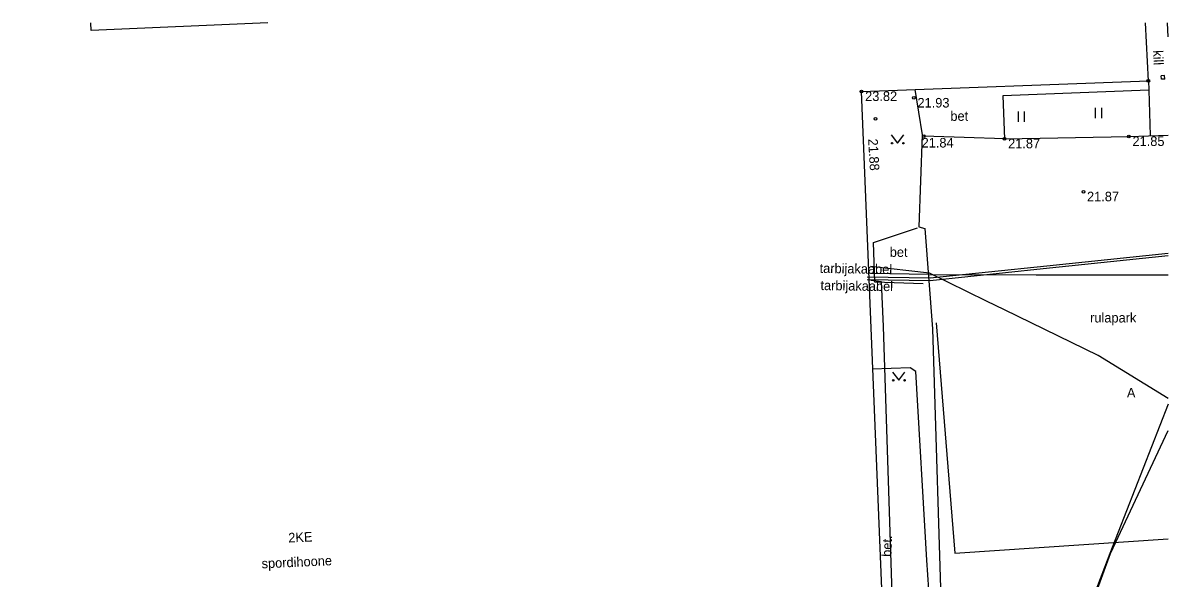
# Model space of a CAD drawing. Extents: x 714038 to 714279, y 6589845 to 6590041.
# Drawn here: x 714195.2 to 714279, y 6590000.4 to 6590041 of the extents above; entities that cross this region are included whole.
import ezdxf

# ---------------------------------------------------------------- set-up
doc = ezdxf.new("R2010")
doc.units = 0
for name, color, linetype in [('AED', 7, 'Continuous'), ('HALJASTUS', 7, 'Continuous'), ('HOONE', 7, 'Continuous'), ('HOONEDET', 7, 'Continuous'), ('KORGUS', 7, 'Continuous'), ('KPKAABEL', 7, 'Continuous'), ('MPKAABEL', 7, 'Continuous'), ('RAJATIS', 7, 'Continuous'), ('TEE', 7, 'Continuous'), ('VTRASS', 7, 'Continuous')]:
    doc.layers.add(name, color=color, linetype=linetype)

msp = doc.modelspace()

# ---------------------------------------------------------------- linework, layer by layer
at = {"layer": 'AED'}
for p, q in [((714278.696, 6590037.106), (714278.446, 6590037.094)), ((714278.458, 6590036.844), (714278.446, 6590037.094)), ((714278.708, 6590036.856), (714278.696, 6590037.106)), ((714278.708, 6590036.856), (714278.458, 6590036.844))]:
    msp.add_line(p, q, dxfattribs=at)
at = {"layer": 'HALJASTUS'}
for p, q in [((714267.973, 6590034.478), (714267.973, 6590033.717)), ((714268.428, 6590034.478), (714268.428, 6590033.717)), ((714273.624, 6590034.747), (714273.624, 6590033.986)), ((714274.079, 6590034.747), (714274.079, 6590033.986)), ((714258.696, 6590032.771), (714259.159, 6590032.164)), ((714259.159, 6590032.164), (714259.605, 6590032.771)), ((714258.777, 6590015.427), (714259.24, 6590014.82)), ((714259.24, 6590014.82), (714259.686, 6590015.427))]:
    msp.add_line(p, q, dxfattribs=at)
msp.add_lwpolyline([(714261.985, 6590019.034), (714263.358, 6590002.185), (714278.95, 6590003.231)], dxfattribs=at)
for centre in [(714258.758, 6590032.164), (714259.587, 6590032.164), (714258.839, 6590014.82), (714259.668, 6590014.82)]:
    msp.add_circle(centre, 0.055, dxfattribs=at)
at = {"layer": 'HOONE'}
for points in [[(714174.151, 6590040.965), (714175.285, 6590011.657), (714176.665, 6589976.107), (714220.25, 6589977.79), (714221.11, 6589977.83), (714221.8, 6589965.63), (714240.53, 6589966.47), (714239.93, 6589984.45), (714258.589, 6589985.264), (714256.524, 6590035.954)], [(714213.081, 6590040.965), (714200.152, 6590040.402), (714200.127, 6590040.965)], [(714256.524, 6590035.954), (714277.505, 6590036.733), (714277.299, 6590040.965)]]:
    msp.add_lwpolyline(points, dxfattribs=at)
at = {"layer": 'HOONEDET'}
msp.add_lwpolyline([(714257.21, 6590022.15), (714257.952, 6590022.053), (714258.109, 6590018.754), (714258.847, 6589996.193)], dxfattribs=at)
at = {"layer": 'KORGUS'}
for centre in [(714277.505, 6590036.733), (714256.524, 6590035.954), (714260.352, 6590035.475), (714257.543, 6590033.939), (714261.083, 6590032.683), (714266.983, 6590032.493), (714276.084, 6590032.663), (714272.758, 6590028.616)]:
    msp.add_circle(centre, 0.1, dxfattribs=at)
at = {"layer": 'KPKAABEL'}
msp.add_lwpolyline([(714278.95, 6590013.083), (714274.696, 6590002.154), (714268.806, 6589986.746), (714264.689, 6589977.209), (714260.118, 6589965.851), (714258.032, 6589961.24), (714253.05, 6589949.372), (714248.466, 6589938.096), (714247.531, 6589934.989), (714246.389, 6589934.367), (714239.483, 6589937.254), (714226.492, 6589940.819), (714222.669, 6589940.979), (714220.982, 6589941.049), (714220.257, 6589940.365), (714218.76, 6589936.611), (714215.836, 6589929.757), (714212.225, 6589922.206), (714208.098, 6589916.26), (714202.344, 6589907.69)], dxfattribs=at)
at = {"layer": 'MPKAABEL'}
for points in [[(714256.928, 6590022.382), (714261.544, 6590022.31), (714270.068, 6590023.197), (714278.95, 6590024.12)], [(714278.95, 6590023.919), (714269.8, 6590022.968), (714261.553, 6590022.11), (714256.933, 6590022.182)], [(714278.95, 6590013.489), (714273.84, 6590016.64), (714266.971, 6590019.986), (714265.675, 6590020.617), (714261.5, 6590022.65), (714257.17, 6590023.14)], [(714261.39, 6590022.56), (714257.19, 6590022.64)], [(714261.39, 6590022.56), (714269.298, 6590022.539), (714272.91, 6590022.53), (714278.95, 6590022.537)], [(714260.237, 6589952.896), (714261.787, 6589959.195), (714262.02, 6589960.932), (714261.884, 6589965.332), (714261.711, 6589970.99), (714261.865, 6589973.126), (714262.509, 6589976.671), (714262.772, 6589980.381), (714262.152, 6589984.091), (714260.918, 6589985.845), (714260.775, 6589986.377), (714261.085, 6589992.906), (714261.893, 6589993.086), (714261.294, 6590001.662), (714260.505, 6590015.467), (714260.091, 6590015.746), (714257.295, 6590015.631)]]:
    msp.add_lwpolyline(points, dxfattribs=at)
at = {"layer": 'TEE'}
msp.add_line((714266.983, 6590032.493), (714261.083, 6590032.683), dxfattribs=at)
for points in [[(714278.95, 6590039.952), (714278.901, 6590040.965)], [(714277.505, 6590036.733), (714277.531, 6590036.033)], [(714260.429, 6590036.093), (714260.958, 6590032.771), (714260.716, 6590026.052), (714261.142, 6590025.936), (714261.703, 6590018.587), (714262.419, 6589995.675)], [(714277.531, 6590036.033), (714266.866, 6590035.638), (714266.983, 6590032.493)], [(714277.531, 6590036.033), (714277.646, 6590032.717)], [(714266.983, 6590032.493), (714276.084, 6590032.663), (714278.95, 6590032.762)], [(714261.034, 6590021.868), (714257.501, 6590022.003), (714257.39, 6590024.898), (714260.617, 6590025.969)]]:
    msp.add_lwpolyline(points, dxfattribs=at)
at = {"layer": 'VTRASS'}
msp.add_lwpolyline([(714263.302, 6589970.808), (714274.743, 6590002.161), (714278.95, 6590011.159)], dxfattribs=at)

# ---------------------------------------------------------------- texts
at = {"layer": 'HOONE'}
for s, p in [('2KE', (714214.595, 6590002.953)), ('spordihoone', (714212.643, 6590001.062))]:
    msp.add_text(s, height=0.7, rotation=2.62072, dxfattribs=at).set_placement(p)
at = {"layer": 'KORGUS'}
for s, p in [(' 23.82', (714256.524, 6590035.254)), (' 21.93', (714260.352, 6590034.775)), (' 21.84', (714260.655, 6590031.851)), (' 21.87', (714266.983, 6590031.793)), (' 21.85', (714276.084, 6590031.963)), (' 21.87', (714272.758, 6590027.916))]:
    msp.add_text(s, height=0.7, dxfattribs=at).set_placement(p)
msp.add_text(' 21.88', height=0.7, rotation=273.31329, dxfattribs=at).set_placement((714256.986, 6590032.736))
at = {"layer": 'MPKAABEL'}
for p in [(714253.449, 6590022.676), (714253.514, 6590021.424)]:
    msp.add_text('tarbijakaabel', height=0.7, rotation=359.11157, dxfattribs=at).set_placement(p)
at = {"layer": 'RAJATIS'}
msp.add_text('rulapark', height=0.7, dxfattribs=at).set_placement((714273.246, 6590019.051))
at = {"layer": 'TEE'}
for s, rotation, p in [('kill', 272.92036, (714277.852, 6590038.949)), ('bet', 0.41008, (714263.023, 6590033.798)), ('bet.', 87.97429, (714258.703, 6590001.899))]:
    msp.add_text(s, height=0.7, rotation=rotation, dxfattribs=at).set_placement(p)
for s, p in [('bet', (714258.585, 6590023.85)), ('A', (714275.936, 6590013.564))]:
    msp.add_text(s, height=0.7, dxfattribs=at).set_placement(p)

doc.saveas('drawing.dxf')
